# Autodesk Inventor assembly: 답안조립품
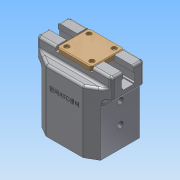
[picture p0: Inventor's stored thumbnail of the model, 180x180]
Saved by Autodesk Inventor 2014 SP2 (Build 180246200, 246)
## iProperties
Created: 2023-05
Part Number: 답안조립품
Document SubType Name: Assembly
Designer: 거성
Author: 거성
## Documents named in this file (7)
- C:\Users\거성\Desktop\730506V1005\답안조립품.iam
- C:\Users\거성\Desktop\730506V1005\본체.ipt
- C:\Users\거성\Desktop\730506V1005\피스톤 로드.ipt
- C:\Users\거성\Desktop\730506V1005\커버.ipt
- C:\Users\거성\Desktop\730506V1005\볼트 M6 x 12.ipt
- C:\Users\거성\Desktop\730506V1005\C형 구멍용 멈춤링 60x2.ipt
- C:\Users\거성\Desktop\730506V1005\앤드캡.ipt
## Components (2 placed, 2 different names)
1. 피스톤 로드:1 — 각도:1
2. C형 구멍용 멈춤링 60x2:1
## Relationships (1: Angle 1)
- 각도:1 [Angle]: 피스톤 로드:1
